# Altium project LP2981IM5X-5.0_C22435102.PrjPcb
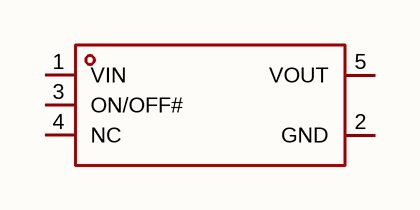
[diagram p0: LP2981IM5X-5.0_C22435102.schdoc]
1 sheet, 1 parts. Net scope: global (net labels, ports and power ports of the same name join across sheets).

## Sheet LP2981IM5X-5.0_C22435102.schdoc
size 127 x 101 mm

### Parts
U?  lp2981im5x-5.0_c22435102  [SOT-23-5_L2.9-W1.6-P0.95-LS2.8-BR]  (value not drawn)

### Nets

Not connected (* = marked no-connect by the designer): U? 1(VIN) 2(GND) 3(ON/OFF#) 4(NC) 5(VOUT)

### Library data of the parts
U? = lp2981im5x-5.0_c22435102: 输出极性:正极;工作电压:18V;输出电压:5V;输出电流:100mA;电源纹波抑制比(PSRR):70dB@(1kHz);输出类型:固定;; Manufacturer: TECH PUBLIC(台舟); AddInBom: yes; ModelId: 7ba65df16e7b4570af156e925f9c37fe; ModelTransform: 114.173,114.173,0,90,0,0,0,0,0; Output Configuration: 正极; Voltage - Supply: 18V; Output Voltage: 5V; Output Current: 100mA; Voltage Dropout: 85mV@(100mA); standby current: 20uA; Output Type: 固定; Number of Outputs: 1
